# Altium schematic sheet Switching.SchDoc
size A4
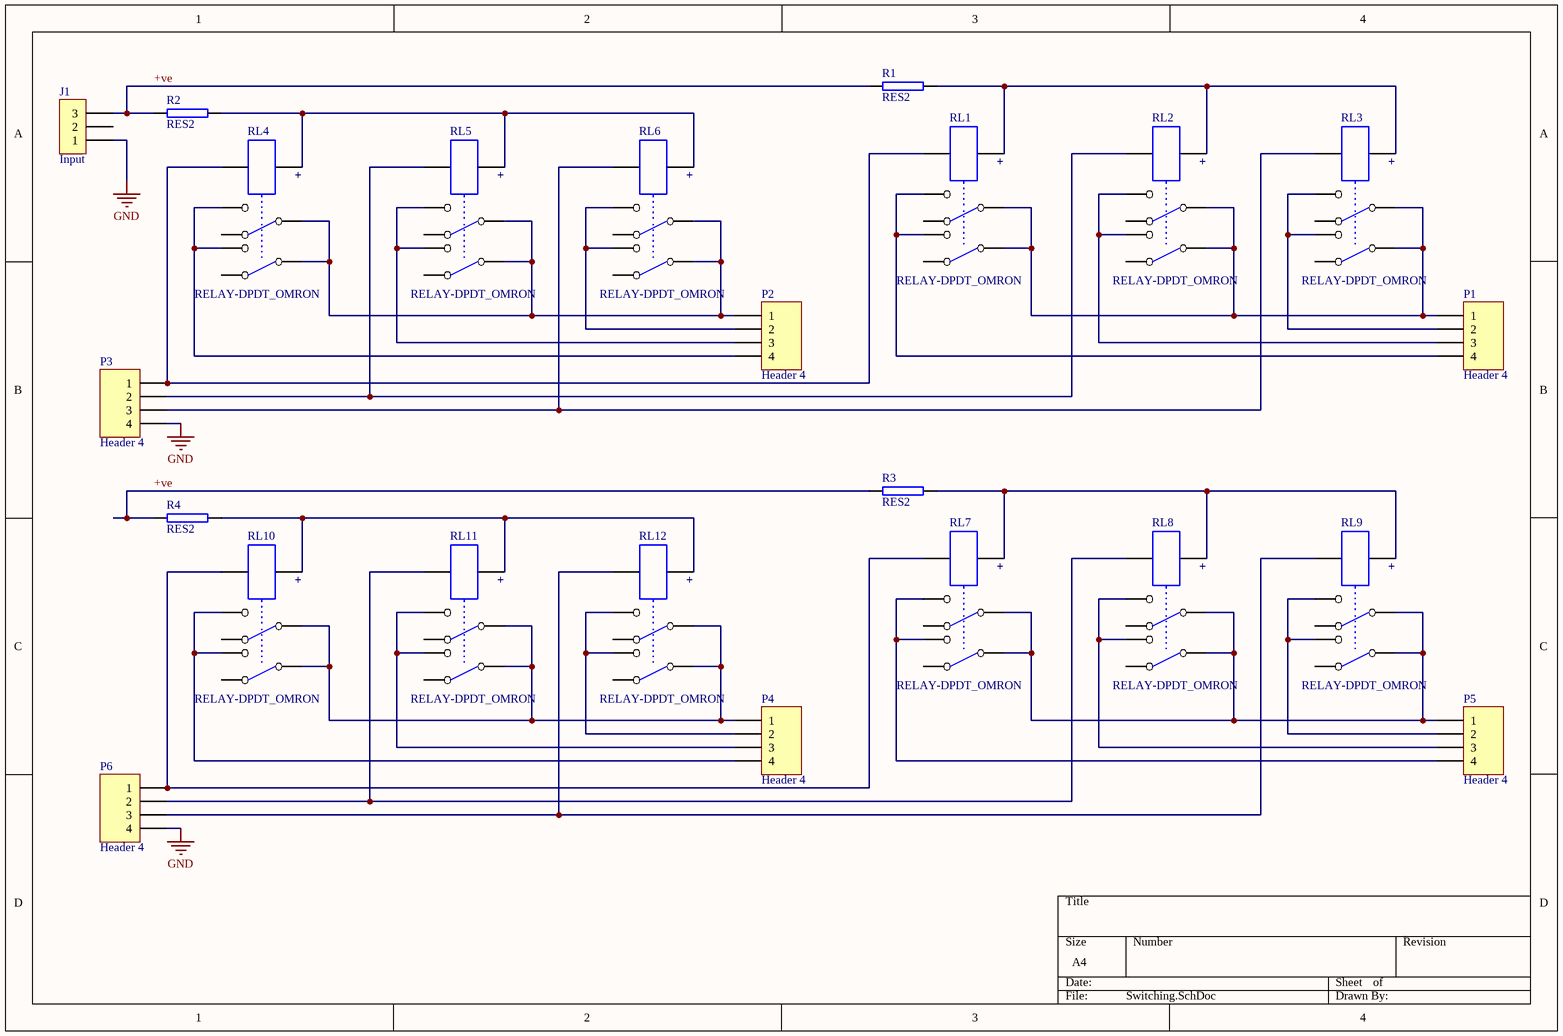
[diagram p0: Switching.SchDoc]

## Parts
J1  Input  [CON3_SCREW]
P1  Header 4  [HDR1X4]
P2  Header 4  [HDR1X4]
P3  Header 4  [HDR1X4]
P4  Header 4  [HDR1X4]
P5  Header 4  [HDR1X4]
P6  Header 4  [HDR1X4]
R1  RES2  [AXIAL0.64]
R2  RES2  [AXIAL0.64]
R3  RES2  [AXIAL0.64]
R4  RES2  [AXIAL0.64]
RL1  RELAY-DPDT_OMRON  [DIP10]
RL2  RELAY-DPDT_OMRON  [DIP10]
RL3  RELAY-DPDT_OMRON  [DIP10]
RL4  RELAY-DPDT_OMRON  [DIP10]
RL5  RELAY-DPDT_OMRON  [DIP10]
RL6  RELAY-DPDT_OMRON  [DIP10]
RL7  RELAY-DPDT_OMRON  [DIP10]
RL8  RELAY-DPDT_OMRON  [DIP10]
RL9  RELAY-DPDT_OMRON  [DIP10]
RL10  RELAY-DPDT_OMRON  [DIP10]
RL11  RELAY-DPDT_OMRON  [DIP10]
RL12  RELAY-DPDT_OMRON  [DIP10]

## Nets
GND: J1.1 P3.4 P6.4
+ve: J1.3 R1.1 R2.1 R3.1 R4.1
NetP1_1: P1.1 RL1.3(In_A) RL1.8(In_B) RL2.3(In_A) RL2.8(In_B) RL3.3(In_A) RL3.8(In_B)
NetP1_2: P1.2 RL3.4(Out_A2) RL3.7(Out_B2)
NetP1_3: P1.3 RL2.4(Out_A2) RL2.7(Out_B2)
NetP1_4: P1.4 RL1.4(Out_A2) RL1.7(Out_B2)
NetP2_1: P2.1 RL4.3(In_A) RL4.8(In_B) RL5.3(In_A) RL5.8(In_B) RL6.3(In_A) RL6.8(In_B)
NetP2_2: P2.2 RL6.4(Out_A2) RL6.7(Out_B2)
NetP2_3: P2.3 RL5.4(Out_A2) RL5.7(Out_B2)
NetP2_4: P2.4 RL4.4(Out_A2) RL4.7(Out_B2)
NetP3_1: P3.1 RL1.10(Coil_-) RL4.10(Coil_-)
NetP3_2: P3.2 RL2.10(Coil_-) RL5.10(Coil_-)
NetP3_3: P3.3 RL3.10(Coil_-) RL6.10(Coil_-)
NetP4_1: P4.1 RL10.3(In_A) RL10.8(In_B) RL11.3(In_A) RL11.8(In_B) RL12.3(In_A) RL12.8(In_B)
NetP4_2: P4.2 RL12.4(Out_A2) RL12.7(Out_B2)
NetP4_3: P4.3 RL11.4(Out_A2) RL11.7(Out_B2)
NetP4_4: P4.4 RL10.4(Out_A2) RL10.7(Out_B2)
NetP5_1: P5.1 RL7.3(In_A) RL7.8(In_B) RL8.3(In_A) RL8.8(In_B) RL9.3(In_A) RL9.8(In_B)
NetP5_2: P5.2 RL9.4(Out_A2) RL9.7(Out_B2)
NetP5_3: P5.3 RL8.4(Out_A2) RL8.7(Out_B2)
NetP5_4: P5.4 RL7.4(Out_A2) RL7.7(Out_B2)
NetP6_1: P6.1 RL7.10(Coil_-) RL10.10(Coil_-)
NetP6_2: P6.2 RL8.10(Coil_-) RL11.10(Coil_-)
NetP6_3: P6.3 RL9.10(Coil_-) RL12.10(Coil_-)
NetR1_2: R1.2 RL1.1(Coil_+) RL2.1(Coil_+) RL3.1(Coil_+)
NetR2_2: R2.2 RL4.1(Coil_+) RL5.1(Coil_+) RL6.1(Coil_+)
NetR3_2: R3.2 RL7.1(Coil_+) RL8.1(Coil_+) RL9.1(Coil_+)
NetR4_2: R4.2 RL10.1(Coil_+) RL11.1(Coil_+) RL12.1(Coil_+)

Not connected (* = marked no-connect by the designer): J1 2; RL1 2(Out_A1) 9(Out_B1); RL2 2(Out_A1) 9(Out_B1); RL3 2(Out_A1) 9(Out_B1); RL4 2(Out_A1) 9(Out_B1); RL5 2(Out_A1) 9(Out_B1); RL6 2(Out_A1) 9(Out_B1); RL7 2(Out_A1) 9(Out_B1); RL8 2(Out_A1) 9(Out_B1); RL9 2(Out_A1) 9(Out_B1); RL10 2(Out_A1) 9(Out_B1); RL11 2(Out_A1) 9(Out_B1); RL12 2(Out_A1) 9(Out_B1)

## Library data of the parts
J1 = CON3: Connector
P1-P6 = Header 4: Header, 4-Pin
